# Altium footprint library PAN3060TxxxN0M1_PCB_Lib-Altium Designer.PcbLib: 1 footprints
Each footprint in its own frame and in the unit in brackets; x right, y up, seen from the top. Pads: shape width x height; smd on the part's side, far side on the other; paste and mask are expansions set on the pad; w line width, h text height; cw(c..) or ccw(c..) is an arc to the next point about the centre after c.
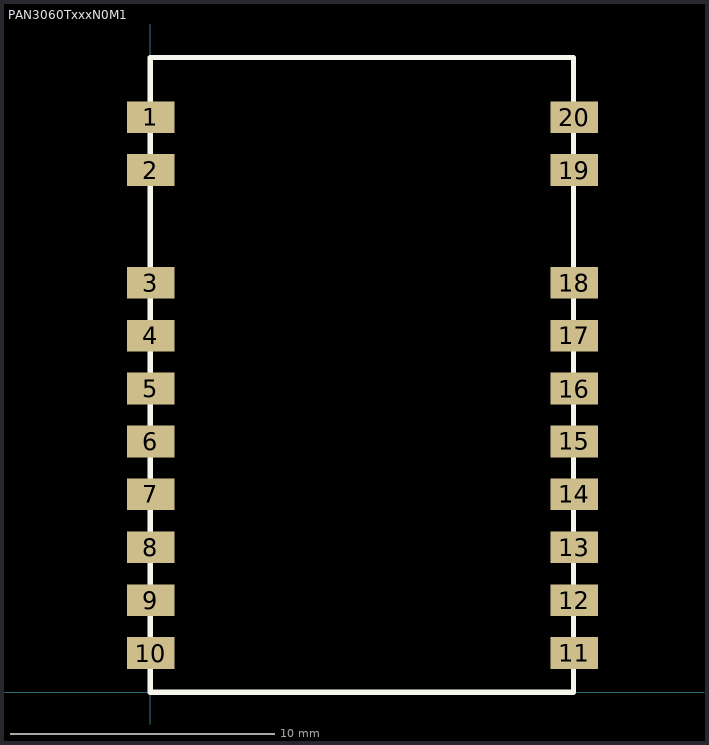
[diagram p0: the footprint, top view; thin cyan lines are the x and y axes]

## PAN3060TxxxN0M1 [mm]
pads (21):
  round 1.2 on Top Overlay: 1(-0.92,23.46)
  rect 1.8x1.2 smd: 1(0.01,21.74) 2(0.01,19.74) 3(0.01,15.48) 4(0.01,13.48) 5(0.01,11.48) 6(0.01,9.48) 7(0.01,7.48) 8(0.01,5.48) 9(0.01,3.48) 10(0.01,1.48) 11(16.02,1.48) 12(16.02,3.48) 13(16.02,5.48) 14(16.02,7.48) 15(16.02,9.48) 16(16.02,11.48) 17(16.02,13.48) 18(16.02,15.48) 19(16.02,19.74) 20(16.02,21.74)
Top Overlay:
  lines w0.2: 0,0 0,24 16.002,24 16.002,0 0,0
